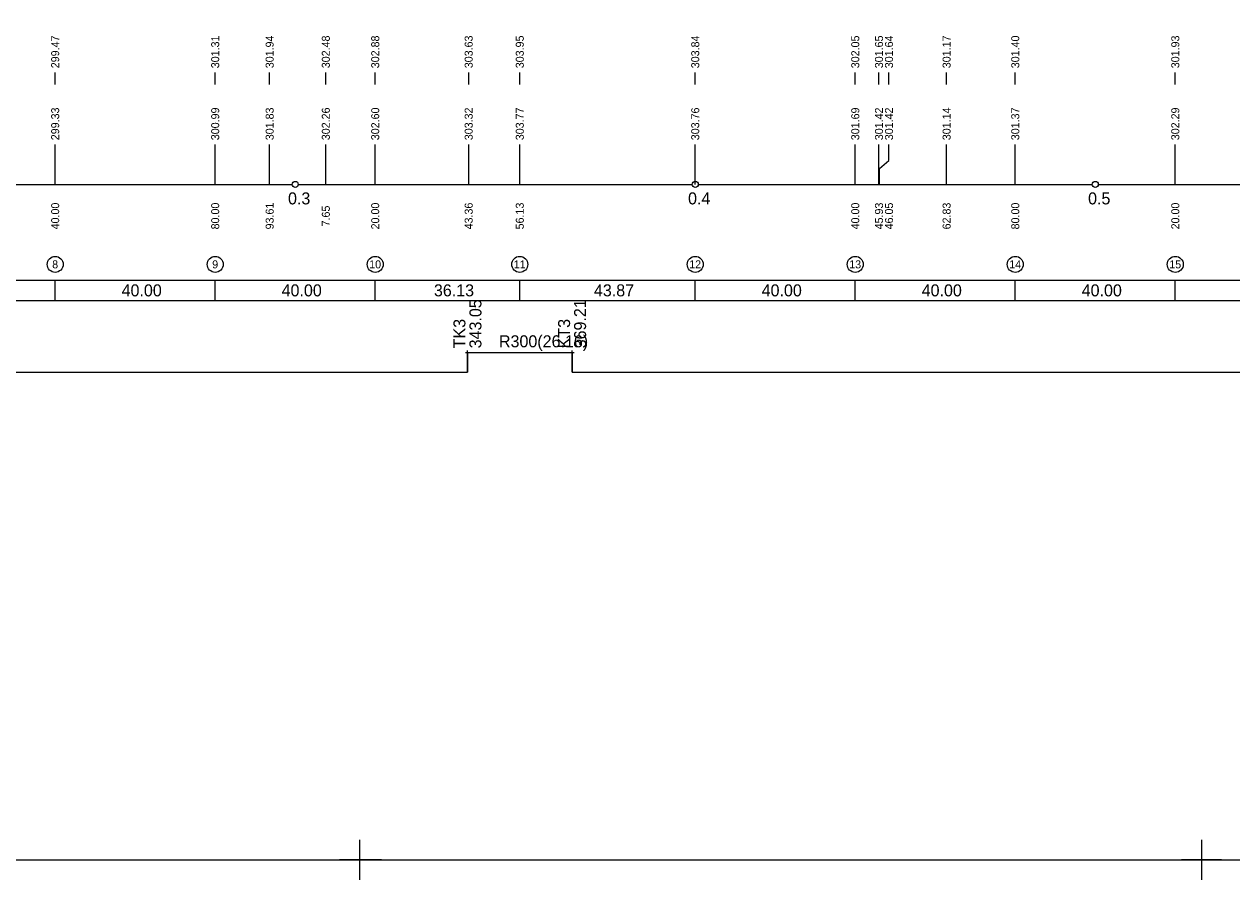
# Model space of a CAD drawing. Extents: x -39 to 1232, y -119 to 485.
# Drawn here: x 302.2 to 604.1, y -118.9 to 95.1 of the extents above; entities that cross this region are included whole.
import ezdxf

# ---------------------------------------------------------------- set-up
doc = ezdxf.new("R2010")
doc.units = 0
for name, color, linetype in [('ramecek', 7, 'Continuous'), ('SESTAVY_REZU_PO', 7, 'Continuous'), ('SMEROVE_POMERY', 7, 'Continuous'), ('SMEROVE_POMERY_KOD', 7, 'Continuous'), ('SVK_STAT', 7, 'Continuous'), ('TABULKY', 7, 'Continuous')]:
    doc.layers.add(name, color=color, linetype=linetype)

msp = doc.modelspace()

# ---------------------------------------------------------------- linework, layer by layer
for p, q in [((386.08, -108.92), (386.08, -118.92)), ((386.08, -108.92), (386.08, -118.92)), ((386.08, -108.92), (386.08, -118.92)), ((596.58, -108.92), (596.58, -118.92)), ((596.58, -108.92), (596.58, -118.92)), ((596.58, -108.92), (596.58, -118.92)), ((596.58, -108.92), (596.58, -118.92)), ((596.58, -108.92), (596.58, -118.92)), ((596.58, -108.92), (596.58, -118.92)), ((596.58, -108.92), (596.58, -118.92)), ((596.58, -108.92), (596.58, -118.92)), ((391.08, -113.92), (381.08, -113.92)), ((391.08, -113.92), (381.08, -113.92)), ((391.08, -113.92), (381.08, -113.92)), ((391.08, -113.92), (381.08, -113.92)), ((391.58, -113.92), (381.58, -113.92)), ((391.58, -113.92), (381.58, -113.92)), ((391.58, -113.92), (381.58, -113.92)), ((391.58, -113.92), (381.58, -113.92)), ((391.58, -113.92), (381.58, -113.92)), ((391.58, -113.92), (381.58, -113.92)), ((391.58, -113.92), (381.58, -113.92)), ((391.58, -113.92), (381.58, -113.92)), ((391.58, -113.92), (381.58, -113.92)), ((391.58, -113.92), (381.58, -113.92)), ((391.58, -113.92), (381.58, -113.92)), ((391.58, -113.92), (381.58, -113.92)), ((601.58, -113.92), (591.58, -113.92)), ((601.58, -113.92), (591.58, -113.92)), ((601.58, -113.92), (591.58, -113.92)), ((601.58, -113.92), (591.58, -113.92)), ((601.58, -113.92), (591.58, -113.92)), ((601.58, -113.92), (591.58, -113.92)), ((601.58, -113.92), (591.58, -113.92)), ((601.58, -113.92), (591.58, -113.92))]:
    msp.add_line(p, q)
at = {"layer": 'ramecek'}
msp.add_lwpolyline([(-34.42, -113.92), (1226.58, -113.92), (1226.58, 480.08), (-34.42, 480.08)], close=True, dxfattribs=at)
at = {"layer": 'SESTAVY_REZU_PO'}
for points in [[(270.75, 55), (369.25, 55)], [(370.75, 55), (469.25, 55)], [(470.75, 55), (569.25, 55)], [(570.75, 55), (669.25, 55)], [(310, 26), (310, 31)], [(350, 26), (350, 31)], [(390, 26), (390, 31)], [(426.13, 26), (426.13, 31)], [(470, 26), (470, 31)], [(510, 26), (510, 31)], [(550, 26), (550, 31)], [(590, 26), (590, 31)]]:
    msp.add_lwpolyline(points, dxfattribs=at)
for centre in [(370, 55), (470, 55), (570, 55)]:
    msp.add_circle(centre, 0.75, dxfattribs=at)
at = {"layer": 'SMEROVE_POMERY'}
msp.add_lwpolyline([(70, 8), (85.35, 8), (85.35, 3), (97.7, 3), (97.7, 8), (105.17, 8), (105.17, 3), (114.98, 3), (114.98, 8), (413.05, 8), (413.05, 13), (413.05, 8), (413.05, 13), (439.21, 13), (439.21, 8), (439.21, 13), (439.21, 8), (796.38, 8)], dxfattribs=at)
at = {"layer": 'SMEROVE_POMERY_KOD'}
for points in [[(412.55, 13), (413.55, 13)], [(412.55, 13), (413.55, 13)], [(413.05, 12.5), (413.05, 13.5)], [(413.05, 12.5), (413.05, 13.5)], [(438.71, 13), (439.71, 13)], [(438.71, 13), (439.71, 13)], [(439.21, 12.5), (439.21, 13.5)], [(439.21, 12.5), (439.21, 13.5)]]:
    msp.add_lwpolyline(points, dxfattribs=at)
at = {"layer": 'SVK_STAT'}
for points in [[(310, 80), (310, 83)], [(350, 80), (350, 83)], [(363.61, 80), (363.61, 83)], [(377.65, 80), (377.65, 83)], [(390, 80), (390, 83)], [(413.36, 80), (413.36, 83)], [(426.13, 80), (426.13, 83)], [(470, 80), (470, 83)], [(510, 80), (510, 83)], [(515.93, 80), (515.93, 83)], [(518.43, 80), (518.43, 83)], [(532.83, 80), (532.83, 83)], [(550, 80), (550, 83)], [(590, 80), (590, 83)], [(310, 55), (310, 65)], [(350, 55), (350, 65)], [(363.61, 55), (363.61, 65)], [(377.65, 55), (377.65, 65)], [(390, 55), (390, 65)], [(413.36, 55), (413.36, 65)], [(426.13, 55), (426.13, 65)], [(470, 55), (470, 65)], [(510, 55), (510, 65)], [(515.93, 55), (515.93, 65)], [(516.05, 55), (516.05, 59), (518.43, 61), (518.43, 65)], [(532.83, 55), (532.83, 65)], [(550, 55), (550, 65)], [(590, 55), (590, 65)]]:
    msp.add_lwpolyline(points, dxfattribs=at)
for centre in [(310, 35), (350, 35), (390, 35), (426.13, 35), (470, 35), (510, 35), (550, 35), (590, 35)]:
    msp.add_circle(centre, 2, dxfattribs=at)
at = {"layer": 'TABULKY'}
msp.add_lwpolyline([(70, 26), (1165.19, 26), (1165.19, 31), (70, 31), (70, 26)], dxfattribs=at)

# ---------------------------------------------------------------- texts
at = {"layer": 'SESTAVY_REZU_PO'}
for s, p in [('0.3', (368.2, 50)), ('0.4', (468.2, 50)), ('0.5', (568.2, 50)), ('40.00', (326.6, 27)), ('40.00', (366.6, 27)), ('36.13', (404.67, 27)), ('43.87', (444.67, 27)), ('40.00', (486.6, 27)), ('40.00', (526.6, 27)), ('40.00', (566.6, 27))]:
    msp.add_text(s, height=3, dxfattribs=at).set_placement(p)
at = {"layer": 'SMEROVE_POMERY'}
msp.add_text('R300(26.16)', height=3, dxfattribs=at).set_placement((420.93, 14.26))
at = {"layer": 'SMEROVE_POMERY_KOD'}
for s, p in [('343.05', (416.55, 14)), ('343.05', (416.55, 14)), ('369.21', (442.71, 14)), ('369.21', (442.71, 14)), ('TK3', (412.55, 14)), ('TK3', (412.55, 14)), ('KT3', (438.71, 14)), ('KT3', (438.71, 14))]:
    msp.add_text(s, height=3, rotation=90, dxfattribs=at).set_placement(p)
at = {"layer": 'SVK_STAT'}
for s, p in [(' 299.47', (311, 83.3)), (' 301.31', (351, 83.3)), (' 301.94', (364.61, 83.3)), (' 302.48', (378.65, 83.3)), (' 302.88', (391, 83.3)), (' 303.63', (414.36, 83.3)), (' 303.95', (427.13, 83.3)), (' 303.84', (471, 83.3)), (' 302.05', (511, 83.3)), (' 301.65', (516.93, 83.3)), (' 301.64', (519.43, 83.3)), (' 301.17', (533.83, 83.3)), (' 301.40', (551, 83.3)), (' 301.93', (591, 83.3)), (' 299.33', (311, 65.3)), (' 300.99', (351, 65.3)), (' 301.83', (364.61, 65.3)), (' 302.26', (378.65, 65.3)), (' 302.60', (391, 65.3)), (' 303.32', (414.36, 65.3)), (' 303.77', (427.13, 65.3)), (' 303.76', (471, 65.3)), (' 301.69', (511, 65.3)), (' 301.42', (516.93, 65.3)), (' 301.42', (519.43, 65.3)), (' 301.14', (533.83, 65.3)), (' 301.37', (551, 65.3)), (' 302.29', (591, 65.3)), (' 40.00', (311, 43)), (' 80.00', (351, 43)), (' 93.61', (364.61, 43)), ('  7.65', (378.65, 43)), (' 20.00', (391, 43)), (' 43.36', (414.36, 43)), (' 56.13', (427.13, 43)), (' 40.00', (511, 43)), (' 45.93', (516.93, 43)), (' 46.05', (519.43, 43)), (' 62.83', (533.83, 43)), (' 80.00', (551, 43)), (' 20.00', (591, 43))]:
    msp.add_text(s, height=2, rotation=90, dxfattribs=at).set_placement(p)
for s, p in [('8', (309.25, 34)), ('9', (349.25, 34)), ('10', (388.49, 34)), ('11', (424.63, 34)), ('12', (468.49, 34)), ('13', (508.49, 34)), ('14', (548.49, 34)), ('15', (588.49, 34))]:
    msp.add_text(s, height=2, dxfattribs=at).set_placement(p)

doc.saveas('drawing.dxf')
